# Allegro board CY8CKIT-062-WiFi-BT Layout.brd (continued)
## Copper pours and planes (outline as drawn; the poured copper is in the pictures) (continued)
VBUS_DEV on L05_MIX: 102.21,61.36 102.21,51.12 101.83,50.74 92.43,50.74 92.05,51.12 92.05,53.92 94.08,55.95 94.08,56.84 94.46,57.22 97.38,57.22 98.91,58.74 98.91,62.22 99.19,62.5 101.07,62.5
VBUS_DISCHARGE on BOTTOM: 19.25,41.88 19.25,45.57 18.62,46.2 16.49,46.2 14.71,44.42 14.71,42.11 14.93,41.88
VBUS_HOST on BOTTOM: 94.67,58.7 94.11,59.26 90.96,59.26 90.96,59.24 90.91,59.24 90.91,57.19 91.14,56.96 94.59,56.96 94.67,57.04
VBUS_HOST on L06_SIG: 84.07,55.99 84.01,56.04 80.91,56.04 80.75,56.2 80.75,59.89 81.25,60.39 83.79,60.39 85.32,61.92 91.16,61.92 93.83,59.25 93.83,57.73 93.45,57.35 86.72,57.35 86.33,56.96 86.33,56.08 86.25,55.99
VBUS_TC on BOTTOM: 46.46,46.94 46.46,46.69 46.71,46.43 46.71,45.66 46.84,45.53 48.11,45.53 48.23,45.66 48.23,46.69 47.8,47.12 46.63,47.12
VBUS_TC on BOTTOM: 37.16,19.65 37.44,19.37 41.58,19.37 41.81,19.6 41.81,21.26 41.77,21.29 41.77,21.77 41.5,22.04 37.44,22.04 37.16,21.76
VBUS_TC on BOTTOM: 11.38,37.66 11.38,46.93 10.96,47.35 8.25,47.35 5.84,49.76 5.16,49.76 5.18,54.42 7.85,54.42 8.36,53.92 8.36,51 8.76,50.59 12.15,50.59 13.64,49.09 30.45,49.09 32.08,50.72 32.08,53.21 33.27,54.4 33.27,58.36 33.45,58.54 35.15,58.54 35.27,58.43 35.27,50.37 35.28,50.36 35.28,44.9 34.14,43.76 27.86,43.76 25.12,46.49 16.35,46.49 14.3,44.44 14.3,37.74 13.94,37.38 11.66,37.38
VBUS_TC on L04_MIX: 23.6,50.49 23.6,29.92 23.8,29.72 23.8,28.83 23.6,28.63 23.6,28.4 23.8,28.19 23.8,27.53 23.6,27.33 23.6,23 26.09,20.52 40.49,20.52 40.87,20.9 40.87,44.52 41.38,45.03 47.35,45.03 47.98,45.66 47.98,52.52 47.6,52.9 44.58,52.9 44.48,52.81 43.54,52.81 43.23,52.5 42.65,52.5 42.65,52.52 42.27,52.9 27.23,52.9 26.94,52.61 25.72,52.61
VCC_1V8 on BOTTOM: 94.27,50.5 94.43,50.34 97.16,50.34 97.39,50.57 97.39,51.46 95.73,53.12 94.39,53.12 94.27,53
VCC_1V8 on BOTTOM: 73.63,52.09 73.63,54.4 73.58,54.45 72.01,54.45 71.69,54.13 71.69,52.32 71.92,52.09
VCC_1V8 on L04_MIX: 79.98,51.76 80.87,52.65 87.1,52.65 87.86,51.88 87.86,50.49 88.24,50.11 95.71,50.11 96.13,50.53 96.13,51.49 95.35,52.27 95.35,54.68 94.97,55.06 87.99,55.06 83.67,59.38 72.36,59.38 71.48,58.49 71.48,52.14 71.86,51.76
VCC_3V3 on TOP: 134.67,51.4 134.67,55.03 134.4,55.3 132.78,55.3 132.74,55.26 132.74,51.4 133.32,50.82 134.09,50.82
VCC_3V3 on TOP: 74.07,48.33 77.55,48.33 77.55,51.52 80.09,54.06 85.86,54.06 85.91,54.01 88.16,54.01 89.1,54.96 89.1,59.33 88.37,60.06 76.05,60.06 72.09,56.1 67.72,56.1 64.29,52.67 59.66,52.67 58.37,51.38 58.37,49.73 55.6,46.96 55.6,39.82 55.58,39.79 55.6,39.77 55.6,35.25 56.36,34.49 56.36,32.71 56.49,32.58 58.52,32.58 59.16,31.95 61.57,31.95 61.7,32.07 61.7,33.22 61.57,33.34 60.17,33.34 60.05,33.47 60.05,36.39 61.32,37.66 61.32,37.74 61.37,37.79 61.37,46.17 63.55,48.35 71.78,48.35 72.26,48.84 72.26,51.05 72.77,51.55 73.89,51.55 74.07,51.38
VCC_3V3 on BOTTOM: 109.97,39.46 109.97,38.5 110.14,38.33 117.51,38.33 117.86,38.68 117.86,39.6 110.11,39.6
VCC_3V3 on BOTTOM: 89.14,56.18 89.14,55.92 88.93,55.71 88.93,54.77 88.9,54.74 87.91,54.74 87.58,55.07 87.58,56.21 87.66,56.29 89.03,56.29
VCC_3V3 on L04_MIX: 48.74,27.12 48.49,26.87 48.49,23.18 48.87,22.8 49.89,22.8 50.52,22.17 59.41,22.17 59.79,22.55 59.79,29.28 61.82,31.31 61.82,36.01 61.32,36.52 49.25,36.52 48.74,36.01
VCC_3V3 on L04_MIX: 101.83,54.68 106.65,54.68 107.04,54.3 107.04,40.58 107.67,39.95 130.53,39.95 132.56,41.98 132.56,52.52 132.94,52.9 135.48,52.9 135.97,52.42 135.97,33.95 135.42,33.4 128.55,33.4 127.98,32.83 99.03,32.83 98.78,33.09 98.78,52.9 98.02,53.66 97.99,53.66 97.99,54.63 97,55.62 96.04,55.62 95.86,55.44 88.11,55.44 86.46,57.09 86.46,60.39 86.72,60.65 93.57,60.65 94.72,59.5 100.69,59.5 101.07,59.12 101.07,55.44
VCC_5V on TOP: 40.49,54.78 40.49,52.65 40.61,52.52 41.71,52.52 42.44,53.26 42.44,54.42 42.37,54.5 41.78,54.5 41.35,54.93 40.64,54.93
VCC_5V on TOP: 62.2,26.36 62.2,22.62 62.79,22.04 64.14,22.04 64.49,22.4 64.49,23.69 64.11,24.07 64.11,24.99 63.79,25.3 63.79,26.68 63.73,26.74 62.59,26.74
VCC_5V on TOP: 63.09,33.09 67.41,33.09 67.54,32.96 67.54,31.31 67.41,31.18 63.22,31.18 62.97,31.44 62.97,32.96
VCC_5V on BOTTOM: 64.24,27.25 64.24,26.1 67.16,26.1 67.16,26.61 67.41,26.87 67.41,28.64 67.67,28.9 67.67,31.56 67.16,32.07 60.3,32.07 59.54,31.31 59.54,28.69 59.69,28.54 62.94,28.54
VCC_5V on BOTTOM: 36.91,55.09 36.91,52.21 37.08,52.04 37.78,52.04 37.92,52.19 37.92,53.41 38.18,53.66 40.24,53.66 40.46,53.44 41.99,53.44 41.99,55.04 41.81,55.22 37.03,55.22
VCC_5V on BOTTOM: 76.33,51.7 74.96,51.7 74.63,51.36 74.63,48.74 75.01,48.36 76.35,48.36 76.48,48.49 76.48,51.55
VCC_5V on BOTTOM: 43.89,44.04 43.89,46.36 43.66,46.59 41.66,46.59 41.35,46.28 41.35,44.4 41.71,44.04
VCC_5V on BOTTOM: 96.32,55.19 93.7,55.19 92.6,54.09 92.6,52.37 90.96,52.37 90.53,52.81 90.53,54.68 91.41,55.57 91.41,56.58 91.53,56.7 95.06,56.7 96.04,57.68 97.16,57.68 98.86,59.38 103.2,59.38 103.53,59.05 103.53,57.68 103.2,57.35 100.25,57.35 100.03,57.12 100.03,56.23 99.75,55.95 97.08,55.95
VCC_5V on BOTTOM: 21.44,31.16 21.44,33.44 21.16,33.72 18.03,33.72 17.55,33.24 17.55,28.97 19.25,28.97
VCC_5V on L05_MIX: 57.89,31.11 57.89,40.84 56.01,42.72 34.85,42.72 22.3,30.17 13.06,30.17 12.67,30.55 12.67,46.75 21.62,55.69 65.38,55.69 68.94,59.25 83.29,59.25 85.32,57.22 93.32,57.22 93.7,56.84 93.7,56.08 91.67,54.04 91.67,52.77 91.29,52.39 78.08,52.39 76.17,50.49 76.17,32.58 75.92,32.33 70.08,32.33 67.28,29.53 67.28,24.68 64.44,21.84 62.51,21.84 61.7,22.65 61.7,27.3
VCC_IN on BOTTOM: 31.57,21.95 32.46,21.95 32.84,22.33 43.98,22.33 45.03,23.39 45.03,24.84 44.75,25.12 32.97,25.12 32.72,24.87 31.57,24.87
VCC_IO_FLASH on BOTTOM: 117.93,40.61 117.93,42.9 117.04,43.79 112.47,43.79 112.47,42.9 115.52,42.9 115.9,42.52 115.9,41 117.17,41 117.55,40.61
VCC_VAR on TOP: 49.91,25.72 49.3,26.33 49.3,30.78 49.35,30.83 50.09,30.83 50.14,30.78 50.14,29.74 51.37,28.5 57.01,28.5 58.42,29.91 63.86,29.91 63.98,29.79 63.98,28.26 63.73,28.01 62.2,28.01 59.92,25.72
VCC_VAR on TOP: 49.63,34.76 49.63,34.54 49.21,34.12 49.21,33.69 49.12,33.6 48.41,33.6 48.41,34.33 48.34,34.41 48.34,34.82 48.43,34.92 49.48,34.92
VCC_VAR on L05_MIX: 48.49,26.87 48.49,34.26 48.31,34.43 48.31,34.82 48.49,34.99 50.9,34.99 51.66,34.23 51.66,30.07 51.61,30.02 51.61,29.05 51.66,29 51.66,26.94 50.44,25.72 49.63,25.72
VDD_NS on TOP: 82.75,46.33 82.75,51.92 81.1,51.92 81.1,46.33
VDDA on TOP: 89.74,35.78 89.74,37.95 93.95,37.95 94.06,37.84 94.06,35.98 93.86,35.78
VDDD on TOP: 87.73,46.55 87.73,48.84 88.62,49.73 88.62,52.01 86.72,52.01 86.59,51.88 86.59,51.5 86.84,51.25 86.84,46.55
VDDD on L05_MIX: 109.83,55.36 111.18,56.71 114.15,56.71 114.4,56.96 114.4,60.14 114.02,60.52 102.97,60.52 102.59,60.14 102.59,51 102.08,50.49 92.18,50.49 91.67,51 91.67,51.88 91.54,52.01 78.21,52.01 76.56,50.36 76.56,32.71 76.94,32.33 81.13,32.33 83.29,34.49 84.68,34.49 85.83,35.63 88.49,35.63 89.64,36.77 89.64,46.04 90.78,47.19 106.53,47.19 109.83,50.49
VDDUSB on TOP: 78.56,48.11 78.56,46.07 72.09,46.07 71.86,46.3 71.86,47.31 72.11,47.57 75.23,47.57 75.77,48.11
VIN on BOTTOM: 1.12,1.77 1.12,3.62 9.12,3.62 11.15,5.66 11.15,8.96 10.64,9.47 10.64,10.1 10.52,10.23 10.02,10.23 9.86,10.39 9.86,12.04 14.17,12.04 14.17,13.28 41,13.28 42.37,14.65 42.37,21.06 46.33,21.06 46.33,19.5 48.11,17.72 48.11,9.97 22.83,9.97 18.11,5.25 18.11,1.08 1.8,1.08
VIN on L04_MIX: 1.18,1.96 1.18,4.83 1.88,5.53 6.5,5.53 7.26,4.78 9.07,4.78 11.15,6.86 11.15,9.06 14.35,12.26 43.79,12.26 44.55,13.02 44.55,18.23 45.69,19.37 48.87,19.37 49.25,18.99 49.25,1.47 48.87,1.08 2.05,1.08
CCG_VBUS_OUT on BOTTOM: 14.94,25.32 14.94,20.11 14.74,19.91 11.28,19.91 11,20.19 11,25.17 11.33,25.5 14.76,25.5
CCG_VDD on TOP: 17.93,53.7 17.93,56.62 17.04,56.62 17.04,53.7
CCG_VDD on BOTTOM: 20.9,54.08 20.9,55.14 20.7,55.35 19.63,55.35 18.11,56.87 17.37,56.87 17.22,56.72 17.22,54.15 17.42,53.95 20.78,53.95
CCG_VSYS on TOP: 42.77,56.56 42.77,53.84 42.88,53.74 43.87,53.74 44.17,54.04 44.17,56.84 43.82,57.19 43.41,57.19
CCG_VSYS on L03_SIG: 14.96,52.01 19.79,56.84 21.69,56.84 25.17,60.32 25.17,60.67 23.89,61.96 22.62,61.96 19.53,58.87 17.48,58.87 13.73,55.12 13.73,52.19 13.91,52.01
CCG_VSYS on L06_SIG: 43.76,56.08 29.57,56.08 26.9,58.74 22.45,58.74 22.22,58.97 22.22,60.75 22.89,61.41 27.15,61.41 29.95,58.62 43.79,58.62 44.2,58.21 44.2,56.51
FRAM_VDD on TOP: 104.75,49.6 104.5,49.34 104.5,43.76 101.7,40.96 101.7,38.68 101.45,38.42 100.56,38.42 100.43,38.55 100.43,41.6 103.35,44.52 103.35,49.85 104.5,51 107.14,51 108.48,52.34 108.48,55.75 109.14,56.41 111.15,56.41 111.38,56.18 111.38,53 107.98,49.6
J1_3V3 on BOTTOM: 49.63,23.31 49.63,22.42 50.01,22.04 50.01,21.53 49.76,21.28 48.23,21.28 48.11,21.4 48.11,22.55 48.87,23.31
J1_3V3 on L04_MIX: 33.63,15.82 34.01,15.44 36.04,15.44 36.42,15.82 36.42,17.21 37.06,17.85 43.66,17.85 45.57,19.75 49.25,19.75 50.27,20.77 50.27,21.91 49.76,22.42 48.36,22.42 47.22,21.28 41.76,21.28 40.61,20.13 34.01,20.13 33.63,19.75
J1_5V0 on TOP: 38.84,16.2 38.84,17.34 41.64,20.15 46.85,20.15 47.32,20.62 47.32,23.08 46.99,23.41 38.3,23.41 35.92,21.02 35.92,16.45 36.8,15.56 38.2,15.56
J1_5V0 on BOTTOM: 46.46,23.31 47.35,23.31 47.85,22.8 47.85,21.4 47.73,21.28 46.08,21.28 45.82,21.53 45.82,22.67
J1_5V0 on BOTTOM: 36.04,15.82 36.42,15.44 38.58,15.44 38.96,15.82 38.96,18.1 38.58,18.48 36.42,18.48 36.04,18.1
KP_PMIC_EN_OUT on BOTTOM: 101.83,53.28 101.68,53.13 99.54,53.13 99.36,53.31 99.36,54.5 100.99,56.13 100.99,56.89 101.19,57.09 103.5,57.09 103.81,56.79 103.81,56.41 101.83,54.42
P5LP_VDD on BOTTOM: 47.83,30.12 47.83,29.49 47.29,28.95 43.68,28.95 42.89,29.74 41.22,29.74 40.74,29.26 40.74,28.98 40.51,28.75 40.16,28.75 40.03,28.88 40.03,29.34 39.7,29.67 37.03,29.67 36.47,30.23 36.47,30.63 36.6,30.76 37.08,30.76 37.52,30.33 43.38,30.33 43.51,30.2 47.75,30.2
P5LP_VDD on BOTTOM: 106.91,58.34 106.91,62.17 106.5,62.58 105.61,62.58 105.23,62.2 105.23,58.34
P5LP_VDD on BOTTOM: 41.76,41.78 42.79,40.74 44.71,40.74 45.06,41.09 45.06,42.79 44.65,43.2 41.91,43.2 41.76,43.05
P5LP_VDD on L05_MIX: 47.6,27.12 48.11,27.63 48.11,34.87 47.6,35.37 47.6,37.15 48.11,37.66 48.11,44.26 47.73,44.65 34.65,44.65 34.01,45.28 34.01,54.93 35.15,56.08 65.13,56.08 68.68,59.63 78.59,59.63 82.27,63.31 100.56,63.31 102.97,60.9 106.58,60.9 107.26,61.59 107.26,64.84 101.96,70.15 1.98,70.15 0.97,69.13 0.97,41.24 0.99,41.22 0.99,6.72 1.93,5.78 12.47,5.78 18.26,11.57 18.26,11.75 26.01,19.5 26.01,25.6 27.53,27.12
P6_PMIC_EN_OUT on BOTTOM: 97.96,48.52 98.78,47.69 101.09,47.69 101.5,48.1 101.5,49.12 101.14,49.47 99.42,49.47 99.29,49.6 99.29,51.63 99.16,51.76 98.02,51.76 97.96,51.69
P6_VDD on TOP: 50.24,33.66 51.71,33.66 52.11,33.26 52.11,31.02 51.82,30.73 51.82,29.33 51.92,29.23 52.65,29.23 52.81,29.38 52.81,33.57 52.12,34.26 50.24,34.26
P6_VDD on TOP: 106.76,47.41 106.86,47.31 109.4,47.31 109.7,47.62 109.7,49.09 106.86,49.09 106.76,48.99
P6_VDD on BOTTOM: 115.93,60.85 115.93,54.09 116.18,53.84 118.01,53.84 118.21,54.04 118.21,58.74 117.65,59.3 117.65,60.83 117.32,61.16 117.32,61.92 117.07,62.17 116.56,62.17 116.31,61.92 116.31,61.23
P6_VDD on BOTTOM: 52.78,29.2 52.78,31.92 52.71,32 51.82,32 51.79,31.97 51.79,30.98 51.77,30.98 51.77,30.94 51.26,30.43 51.26,29.3 51.36,29.2
P6_VDD on BOTTOM: 121.75,38.26 122.39,38.9 122.39,40.26 122.15,40.51 119.61,40.51 118.75,39.64 118.29,39.64 118.19,39.54 118.19,38.57 118.5,38.26
P6_VDD on BOTTOM: 49.61,3.02 49.61,1.12 45.34,1.12 45.34,3.02
P6_VDD on L05_MIX: 18.77,11.5 26.52,19.25 26.52,21.66 26.9,22.04 48.62,22.04 49.25,22.67 49.25,23.82 52.04,26.61 52.04,29.02 51.87,29.2 51.87,29.89 52.04,30.07 52.04,34.36 51.16,35.25 51.16,41.34 51.41,41.6 56.62,41.6 57.51,40.71 57.51,30.68 59.28,28.9 59.31,28.9 61.44,26.76 64.9,26.76 70.08,31.95 81.37,31.95 83.53,34.1 84.81,34.1 85.95,35.25 88.62,35.25 90.02,36.64 90.02,46.04 90.78,46.8 106.4,46.8 110.21,50.61 110.21,53.15 110.23,55.15 111.23,56.2 111.35,56.33 114.53,56.33 114.91,55.95 117.73,55.95 118.11,55.57 118.11,45.76 119.05,44.82 126.72,44.82 127.28,44.26 127.28,42.08 122.73,37.53 100.94,37.53 97.49,34.08 97.49,34.05 94.01,30.58 84.74,30.58 84.25,30.08 84.25,17.23 87.18,14.3 87.18,11.75 87.84,11.09 87.84,1.08 19.15,1.08 18.77,1.47
SHIELD on TOP: 98.25,1.02 98.25,32.07 135.84,32.07 135.84,1.02 ; 1 cut-out
SHIELD on BOTTOM: 98.25,1.02 98.25,32.07 135.84,32.07 135.84,1.02
USB_TC_PWR_SENSE on BOTTOM: 14.81,28.04 14.81,35.94 13.94,36.8 11.63,36.8 11.63,28.04
VBACKUP on TOP: 84.05,49.34 84.05,45.79 85.45,45.79 85.45,49.34
VBACKUP on BOTTOM: 106.69,50.6 107.11,51.02 107.11,52.47 106.95,52.63 105.61,52.63 105.45,52.47 103.56,52.47 102.72,51.63 102.72,50.69 102.81,50.6
VBACKUP on L04_MIX: 97.89,53.28 98.4,52.77 98.4,46.3 98.02,45.92 84.56,45.92 84.18,46.3 84.18,49.34 84.56,49.73 96.11,49.73 96.75,50.36 96.75,51.76 96.7,51.76 96.11,52.34 96.11,55.26 96.19,55.34 96.85,55.34 97.89,54.3
VTARG on TOP: 92.56,35.4 92.56,33.67 92.68,33.55 95.15,33.55 95.33,33.72 95.33,35.27 95.2,35.4
VTARG on TOP: 86.56,49.63 86.56,51.92 83.13,51.92 83.13,49.63
VTARG on BOTTOM: 59.16,28.14 59.28,28.26 59.28,31.44 60.43,32.58 60.43,39.18 59.28,40.33 56.87,40.33 56.24,39.69 56.24,32.83 56.74,32.33 56.74,28.26 56.87,28.14
VTARG on BOTTOM: 75.22,45.12 75.41,44.92 76.4,44.92 76.66,45.18 76.66,46.76 76.47,46.94 75.36,46.94 75.22,46.8
VTARG on L04_MIX: 78.08,32.33 74.88,32.33 74.31,32.89 69.39,32.89 69.34,32.94 68.63,32.94 68.01,32.33 63.43,32.33 62.2,33.55 62.2,36.26 61.57,36.9 55.73,36.9 55.35,37.28 55.35,46.04 55.73,46.42 72.87,46.42 74.02,47.57 74.02,51 74.4,51.38 79.98,51.38 80.87,52.27 87.1,52.27 87.48,51.88 87.48,50.49 87.1,50.11 84.56,50.11 83.79,49.34 83.79,46.17 84.43,45.53 96.75,45.53 97.13,45.15 97.13,33.72 96.75,33.34 86.08,33.34 86.02,33.28 79.03,33.28
VTARG_BUF on TOP: 72.75,51.02 72.75,48.73 72.9,48.58 73.76,48.58 73.76,51.02 73.56,51.22 72.95,51.22
VTARG_BUF on BOTTOM: 73.91,50.6 73.33,51.18 71.65,51.18 71.48,51 71.48,47.44 72.97,47.44 73.91,48.39
VTARG_BUF on BOTTOM: 49.27,27.9 49.35,27.98 49.35,28.62 49.91,29.18 49.91,30.17 49.86,30.22 48.18,30.22 48.13,30.17 48.13,28.04 48.28,27.9
VTARG_IN on BOTTOM: 67.67,26.99 67.79,26.87 69.88,26.89 70.15,27.17 70.15,27.5 69.86,27.79 69.86,30.26 69.7,30.42 68.05,30.42 67.92,30.29 67.92,28.64 67.67,28.39
VTARG_IN on L03_SIG: 59.08,4.08 59.08,1.03 67.89,1.03 67.89,3.78 67.59,4.08
VTARG_IN on L04_MIX: 68.29,1.04 59.11,1.04 59.11,4.13 61.32,4.13 61.44,4.01 61.44,2.48 61.7,2.23 64.36,2.23 65.13,2.99 65.13,5.91 66.52,7.31 66.52,20.77 67.67,21.91 67.67,29.26 68.08,29.68 74.26,29.68 74.52,29.41 74.52,2.86 73,1.34
VTARG_REF on BOTTOM: 50.24,1.12 50.24,5.05 51.77,5.05 52.91,3.91 74.37,3.91 74.37,1.12
WL_VBAT on TOP: 128.99,53.88 132.14,53.88 132.14,55 132.07,55.07 128.92,55.07 128.92,53.95
WL_VDDIO on BOTTOM: 120.7,57.27 121.81,57.27 122.34,57.8 122.34,59.21 122.71,59.58 124.13,59.58 124.21,59.5 124.21,58.74 124.98,58.74 125.13,58.89 125.13,61.1 123.76,62.48 119.35,62.48 118.06,61.18 118.06,59.4 118.08,59.4 118.08,59.25 118.25,59.09 118.88,59.09
N17715329 on TOP: 30.81,23.6 30.81,24.74 31.7,25.63 31.7,32.77 31.8,32.87 33.38,32.87 33.48,32.77 33.48,25.25 31.7,23.47 30.94,23.47
N17715329 on BOTTOM: 31.32,32.44 31.32,27.99 31.78,27.53 33.31,27.53 33.6,27.83 33.6,32.69 33.43,32.87 31.75,32.87
N17715335 on TOP: 30.3,23.6 30.3,24.74 29.16,25.88 29.16,32.66 28.96,32.87 27.38,32.87 27.25,32.74 27.25,25.63 29.41,23.47 30.18,23.47
N17715335 on BOTTOM: 27.25,32.87 27.25,27.73 27.45,27.53 28.86,27.53 29.79,28.47 29.79,32.08 29.01,32.87
N17831172 on BOTTOM: 45.8,7.69 45.8,4.29 49.23,4.29 49.23,7.69
N17831185 on BOTTOM: 41.38,9.59 41.38,8.2 48.97,8.2 48.97,9.59
N17831187 on BOTTOM: 45.03,4.29 45.03,7.98 41.99,7.98 41.99,4.29
N18103720 on BOTTOM: 43.64,56.24 43.64,53.95 43.76,53.82 44.65,53.82 44.78,53.95 44.78,55.73 45.42,56.36 46.41,56.36 46.71,56.67 46.71,60.6 46.38,60.93 44.55,60.93 44.55,57.15
N18205161 on BOTTOM: 20.75,40.38 16.38,40.38 15.7,39.69 15.7,36.31 16.08,35.93 21.23,35.93 21.23,39.9
N18323131 on BOTTOM: 12.48,14.07 9.73,14.07 9.73,16.81 10.36,17.44 13.28,17.44 13.64,17.09 13.64,15.23
N18323606 on BOTTOM: 26.52,54.81 26.52,53.54 26.64,53.41 29.44,53.41 29.62,53.59 29.62,54.84 29.46,55 26.71,55
N18323726 on BOTTOM: 27.65,56.6 27.25,57 27.25,59.78 25.88,61.16 14.07,61.16 12.22,63.01 2.95,63.01 2.13,63.82 2.13,66.74 2.51,67.12 13.82,67.12 17.88,63.06 26.21,63.06 26.34,62.93 29.21,62.93 31.19,60.95 31.19,57.27 30.52,56.6
N18810466 on BOTTOM: 56.36,32.45 56.49,32.33 56.49,28.39 56.11,28.01 54.33,28.01 54.08,28.26 54.08,32.2 54.33,32.45
N18810466 on L06_SIG: 49.77,29.65 48.74,30.68 48.74,32.33 49.38,32.96 52.04,32.96 52.49,33.41 56.54,33.41 56.9,33.04 56.9,30.57 55.98,29.65
N18852351 on TOP: 127.79,59.07 128.8,58.06 128.8,56.79 128.85,56.74 130.12,56.74 130.12,58.82 128.68,60.27 127.86,60.27 127.79,60.19
N18903176 on BOTTOM: 101.02,44.16 105.41,44.16 105.41,48.81 105.08,49.14 102.69,49.14 102.54,48.99 102.54,47.13 101.02,45.61

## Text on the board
BOTTOM: BOTTOM SIDE
Ref Des/Assembly Bottom: ASSEMBLY BOTTOM
Board Geometry/Soldermask Bottom: SOLDERMASK BOTTOM
Ref Des/Silkscreen Bottom: 1 | J10 | J16 | J7 | J9 | J6 | BAT CON | D | H | E | J19 | J3 | 5 | J14 | B | J1 | J18 | SENSE | CURRENT | 3 | PWR MON | J12 | J5 | J2 | J11 | CCG_SWDCLK | CCG_SWDIO | CCG_VSYS | CCG_XRES_L | GND | SUPER CAP | J28 | VDDD/ | PSoC 6 | KITPROG2 | SUPER CAP/ | K | VBACKUP/PMIC CTRL | P3.5 | P4.0 | P3.4 | P2.7 | P2.6 | 11.1 | 0.3 | 1.1 | SW1 | SW2 | R | 0.4 | RST | LED5 | G | P6.VDD | 5.2(RTS) | 5.3(CTS) | 5.0(RX) | 5.1(TX) | 12.1 | 12.2 | 12.4 | 12.0 | 6.0 | 6.1 | UART CTS | SPI SSEL | UART RTS | SPI SLCK | SPI MOSI | SPI MISO | UART TX | UART RX | I2C SCL | I2C SDA | 15.1 | 12.5 | 15.2 | 15.3 | PSoC 5 LP | 1.6(RTS) | 12.6(TX) | 12.7(RX) | 15.5(CTS) | SILKSCREEN BOTTOM
TOP: TOP SIDE
Ref Des/Assembly Top: 1 | ASSEMBLY TOP
Board Geometry/Soldermask Top: SOLDERMASK TOP
Ref Des/Silkscreen Top: 1 | GND | KITPROG2 | PD OUT | CHARGE | P5LP | SWD | PSoC 5LP I/Os | RST | VDD | USB | VIN | 3 | A1 | 2 | USB PD | . | 5 | 4 | 6 | OUT | I | C | 7 | O | L | K | 0 | 15.5 | J15 | 0.4 | CUSTOM APP | MODE SELECT | POWER | VCC.5V | 40 | LED | STATUS | LEDs | PMOD | CY8C5868LTI-LP039 | CURRENT | SENSE | P6 DEBUG & TRACE | P6.VDD | BAT NTC I/P | VCC.3V3 | NC | VDD.NS | VRF | 19 | 20 | P6 PROG | 1.8V-3.3V | VDD SELECT | VARIABLE | 1.8V | 3.3V | PSoC 6 | B | 8.0 | PROXIMITY | VCCD | A | TX | USB DEVICE | BTN0 | (1.0) | VDDD | S25FL512S | (8.1) | RX0 | 11 | SLIDER | (8.2) | RX1 | VDDA | LBEE5KL1DX | BTN1 | ( | SCL | P6VDD | SDA | F | E | R | V | 12 | D | N | G | 13 | D9 | D8 | 8 | D7 | D6 | ) | A0 | 10 | 9 | D5 | D4 | D3 | A2 | D2 | A3 | D1 | A4 | A5 | D0 | USB HOST | SLD0(8.3) | F-RAM.VDD | SLD1(8.4) | SLD2(8.5) | SLD3(8.6) | SLD4(8.7) | SILKSCREEN TOP
L02_GND: L02_GND
L03_SIG: L03_SIG
L04_MIX: L04_MIX
L05_MIX: L05_MIX
L06_SIG: L06_SIG
L07_GND: L07_GND
PAGE_OUTLINE: SOLDERPASTE TOP
DIMENSION: X4 | SOLDERPASTE BOTTOM
User.6: GOLDMASK TOP
User.7: GOLDMASK BOTTOM
User.23: 2
User.45: FIGURE | SIZE | 0.0059 | 0.0098 | 0.0120 | 0.0130 | 0.0158 | 0.0276 | 0.0295 | 0.0374 | 0.0394 | 0.0402 | 0.0453 | 0.0512 | 0.0906 | 0.0354 | 0.0630x0.0236 | 0.0374x0.0295 | DRILL CHART: TOP to BOTTOM | ALL UNITS ARE IN INCHES | TOLERANCE | +0.0020/-0.0059 | +0.0020/-0.0098 | +0.0000/-0.0000 | +0.0030/-0.0030 | +0.0020/-0.0020 | PLATED | NON-PLATED | QTY | 97 | 1092 | 5 | 6 | 24 | 2 | 30 | 1 | 4 | 110 | 26
